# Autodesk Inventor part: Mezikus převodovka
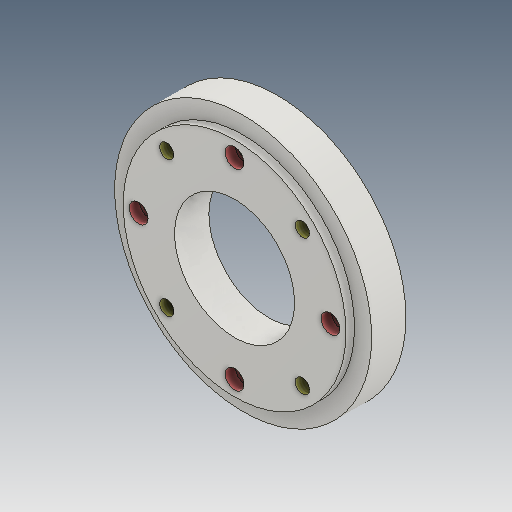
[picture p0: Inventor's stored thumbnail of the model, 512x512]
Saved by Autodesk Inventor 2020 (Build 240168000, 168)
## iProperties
Created: 2025-03
Part Number: Mezikus převodovka
Material: Ocel
Document SubType Name: Modeling
Designer: doma
Density: 7.85 g/cm^3
Appearance: Ocel
Mass: 2100.79 g
Surface Area: 489.704 cm^2
Volume: 267.616 cm^3
Author: doma
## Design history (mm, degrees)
sketch "Náčrt1"
  geometry: C1 r 75 at (0, 0); 1 further point
  constraints: 1 centre point, 1 coincident
  dimensions: "d0" = 150 diameter of C1
extrude "Vysunutí1" new body sketch "Náčrt1" distance "d1" = 20; taper "d2" = 0 deg
sketch "Náčrt2"
  geometry: C1 r 65 at (0, 0); 1 further point
  constraints: 1 centre point, 1 coincident
  dimensions: "d3" = 130 diameter of C1
extrude "Vysunutí2" join sketch "Náčrt2" distance "d4" = 5; taper "d5" = 0 deg
sketch "Náčrt3"
  geometry: C1 r 35 at (0, 0); 1 further point
  constraints: 1 centre point, 1 coincident
  dimensions: "d6" = 70 diameter of C1
extrude "Vysunutí3" cut sketch "Náčrt3" extent not by distance; stored distance "d7" = 0; taper "d8" = 0 deg
sketch "Náčrt4"
  geometry: C1 r 35 at (0, 0) reference; C2 r 65 at (0, 0); 1 further point
  constraints: 1 centre point, 1 coincident
  dimensions: "d9" = 130 diameter of C2
extrude "Vysunutí4" cut sketch "Náčrt4" distance "d10" = 5; taper "d11" = 0 deg
sketch "Náčrt5" dims "d12" = 112
  geometry: 10 further points
  constraints: 1 coincident, 1 vertical alignment, 11 other
  dimensions: "d15" = 360 deg dimension on point (0, 0) point (0, 56) (derived)
hole "Díra1" sketch "Náčrt5" at (-39.598, 39.598), (-39.598, -39.598), (39.598, -39.598), (39.598, 39.598) diameter "d17" = 8.376; stored, may be unused: countersink angle "d21" = 90 deg, drill point angle "d23" = 118 deg; dims "d18" = 20, "d19" = 4, "d20" = 2, "d22" = 27.3
sketch "Náčrt6"
  geometry: 5 further points
  constraints: 5 other
  dimensions: "d24" = 56 distance of point (0, 56) point (0, 0); "d27" = 360 deg dimension on point (0, 0) point (0, 56) (derived)
hole "Díra2" sketch "Náčrt6" at (0, 56), (-56, 0), (0, -56), (56, 0) diameter "d29" = 7; stored, may be unused: countersink angle "d33" = 90 deg, drill point angle "d35" = 118 deg; dims "d30" = 20, "d31" = 11, "d32" = 6, "d34" = 28
node "Těleso1"
